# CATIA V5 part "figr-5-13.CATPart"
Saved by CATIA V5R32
Part number: Part1
Bounding box of the stored display mesh (mm): x 0 to 150, y -70 to 70, z -150 to 69.804
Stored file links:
  D:\PROJECTS\Project 2022\CATIA V5 6R 2022\Resources\Part Files\c05_catia_v5_6r2022_prt\figr-5-13.CATPart
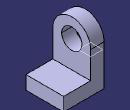
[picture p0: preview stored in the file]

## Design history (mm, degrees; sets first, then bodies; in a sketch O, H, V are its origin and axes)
Set1
  Plane1: type Normal, Curve edge [face of Pad1 | face of Pad1], RefPoint vertex of Pad2
Body1 (main body)
  Sketch1 on yz-plane, origin (0, 0, 0), H (0, 1, 0), V (0, 0, 1)
    arc A1 centre (0, 0) radius 70 from (70, 0) to (-70, 0) ccw
    point P1 (70, 0)
    point P2 (-70, 0)
    line L1 (-70, 0) -> (-70, -150)
    line L2 (-70, -150) -> (70, -150)
    line L3 (70, -150) -> (70, 0)
    circle A2 centre (0, 0) radius 37.5
    radius A1 = 70
    radius A2 = 37.5
    distance O L2 = 150
    coincidence: P1 H, P2 H
    tangency: L1 A1, L3 A1
    horizontal: L2 H
  Pad1: profile Sketch1, direction (1, 0, 0), length 50
  Sketch2 on face of Pad1, origin (50, 0, 0), H (0, 1, 0), V (0, 0, 1)
    line L1 (-70, -150) -> (70, -150)
    line L2 (70, -150) -> (70, -100)
    line L3 (70, -100) -> (-70, -100)
    line L4 (-70, -100) -> (-70, -150)
    reference projected line E1 (-70, -150) -> (70, -150) from edge [face of Pad1 | face of Pad1]
    reference projected line E2 (-70, 0) -> (-70, -150) from edge [face of Pad1 | face of Pad1]
    reference projected line E3 (70, -150) -> (70, 0) from edge [face of Pad1 | face of Pad1]
    length L2 = 50
    horizontal: L1 H, L3 H
    vertical: L2 V, L4 V
    coincidence: L1 E1, E2 L4, L2 E3
  Pad2: profile Sketch2, direction (1, 0, 0), length 100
